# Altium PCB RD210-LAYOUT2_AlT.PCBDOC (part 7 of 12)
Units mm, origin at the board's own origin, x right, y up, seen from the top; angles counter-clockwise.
Board outline 250 x 123 mm, 4 copper layers (TOP, Mid-Layer 1, Mid-Layer 2, BOTTOM), stack 0.711 mm thick; 1043 components, 659 nets, 2786 pads, 1228 vias.
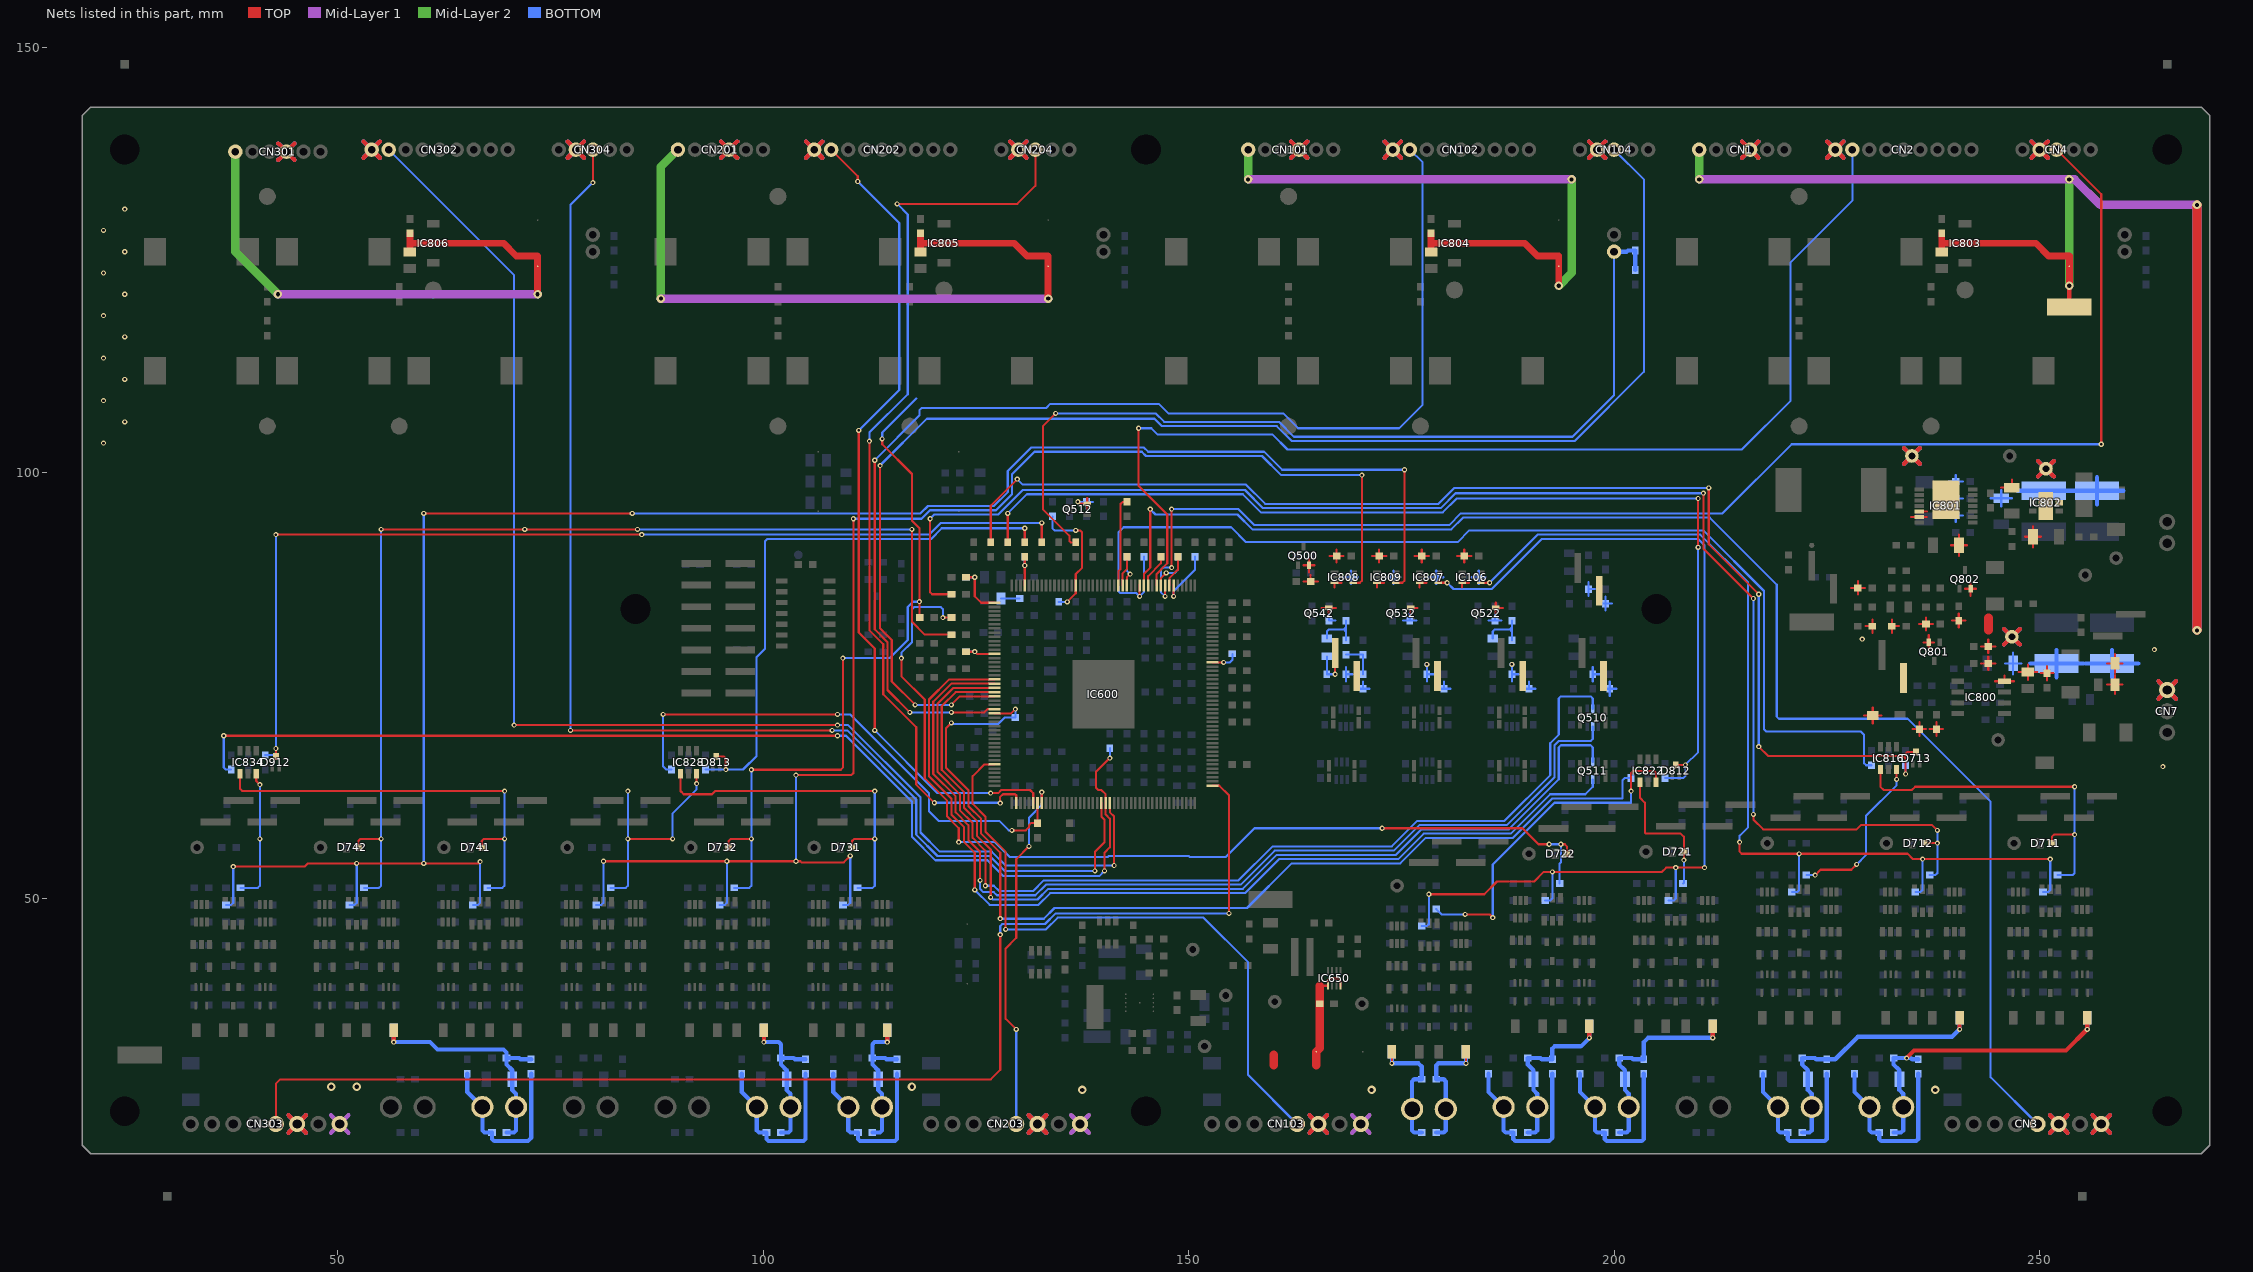
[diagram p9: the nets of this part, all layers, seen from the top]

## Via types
v1: diameter 0.6, hole 0.3, TOP to BOTTOM, 1134 vias
v2: diameter 1, hole 0.5, TOP to BOTTOM, 94 vias

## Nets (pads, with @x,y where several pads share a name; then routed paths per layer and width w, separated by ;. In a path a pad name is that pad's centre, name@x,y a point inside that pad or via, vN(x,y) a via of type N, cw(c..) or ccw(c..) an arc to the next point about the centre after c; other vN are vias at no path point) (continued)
GND: C501.1 C502.1 C517.1 C518.1 C527.1 C528.1 C537.1 C538.1 C547.1 C548.1 C635.1 C636.1 C637.1 C648.1 C650.2 C651.1 C801.1 C812.1 C813.1 C814.2 C816.1 C817.1 C818.1 C819.1 C820.1 C836.1 C837.1 CN1.3 CN2.9 CN3.3 CN4.4 CN101.3 CN102.9 CN103.3 CN104.4 CN201.3 CN202.9 CN203.3 CN204.4 CN301.3 CN302.9 CN303.3 CN304.4 CN400.2 CN500.2 CN510.2 CN520.2 CN530.2 CN540.2 CN955.1 CN956.1 IC106.3 IC650.5 IC650.8 IC801.5 IC801.6 IC801.15 IC802.2 IC802.7 IC807.3 IC808.3 IC809.3 pad.@178,77.5 pad.@188,77.5 Q500.2 Q512.2 Q522.2 Q532.2 Q542.2 Q801.2 Q802.2 R505.1 R568.1 R578.1 R588.1 R598.1 R635.2 R636.2 R637.2 R648.2 R803.1 R811.1 R815.1 | length 547.6
  TOP w0.25: 137.275,96.4 Q512.2@138.1,96.4 ; 138.1,95.775 Q512.2@138.1,96.4 ; 138.1,97.025 Q512.2@138.1,96.4 ; 163.525,87.25 R505.1@164.35,87.25 ; 163.525,89.15 Q500.2@164.15,89.15 ; 164.15,88.325 Q500.2@164.15,89.15 ; 164.15,89.975 Q500.2@164.15,89.15 ; 164.35,88.025 R505.1@164.35,87.25 ; 164.775,89.15 Q500.2@164.15,89.15 ; 165.175,87.25 R505.1@164.35,87.25 ; 165.65,39.5 165.4,39.75 IC650.5@166.375,39.75 ; 165.65,84.15 Q542.2@166.475,84.15 ; IC650.5@166.375,39.5 IC650.5@166.375,39.75 ; 166.475,83.525 Q542.2@166.475,84.15 ; 166.575,90.25 C636.1@167.4,90.25 ; 167.15,86.575 IC808.3@167.15,87.1 167.975,87.1 ; 167.3,84.15 Q542.2@166.475,84.15 ; 167.4,89.475 C636.1@167.4,90.25 ; 167.4,91.025 C636.1@167.4,90.25 ; IC650.8@167.875,39.75 167.875,40.375 167.625,40.625 166.625,40.625 166.375,40.375 IC650.5@166.375,39.75 ; 168.225,90.25 C636.1@167.4,90.25 ; 171.575,90.25 C637.1@172.4,90.25 ; 172.15,86.575 IC809.3@172.15,87.1 172.975,87.1 ; 172.4,89.475 C637.1@172.4,90.25 ; 172.4,91.025 C637.1@172.4,90.25 ; 173.225,90.25 C637.1@172.4,90.25 ; 176.1,83.525 Q532.2@176.1,84.15 176.925,84.15 ; 176.575,90.25 C635.1@177.4,90.25 ; 177.15,86.575 IC807.3@177.15,87.1 177.975,87.1 ; 177.4,89.475 C635.1@177.4,90.25 ; 177.4,91.025 C635.1@177.4,90.25 ; 178.225,90.25 C635.1@177.4,90.25 ; 181.575,90.25 C648.1@182.4,90.25 ; 182.15,86.575 IC106.3@182.15,87.1 182.975,87.1 ; 182.4,89.475 C648.1@182.4,90.25 ; 182.4,91.025 C648.1@182.4,90.25 ; 183.225,90.25 C648.1@182.4,90.25 ; 186.1,83.525 Q522.2@186.1,84.15 ; 186.1,84.775 Q522.2@186.1,84.15 ; 186.925,84.15 Q522.2@186.1,84.15 ; 227.825,86.5 C819.1@228.65,86.5 ; 228.65,85.725 C819.1@228.65,86.5 ; 228.65,87.275 C819.1@228.65,86.5 ; 229.475,86.5 C819.1@228.65,86.5 ; 229.525,82 C801.1@230.35,82 ; 230.35,81.225 C801.1@230.35,82 ; 230.35,82.775 C801.1@230.35,82 ; 232.65,81.225 C820.1@232.65,82 ; 232.65,82.775 C820.1@232.65,82 ; 233.475,82 C820.1@232.65,82 ; 234.925,94.825 IC801.6@235.85,94.825 236.775,94.825 ; 235.825,82.25 R803.1@236.65,82.25 ; IC801.5@235.85,95.475 236.775,95.475 ; 236.35,80.1 Q801.2@236.975,80.1 ; 236.65,81.475 R803.1@236.65,82.25 ; 236.65,83.025 R803.1@236.65,82.25 ; 236.975,79.275 Q801.2@236.975,80.1 ; 236.975,80.925 Q801.2@236.975,80.1 ; 237.475,82.25 R803.1@236.65,82.25 ; 237.6,80.1 Q801.2@236.975,80.1 ; 239.575,91.5 C818.1@240.525,91.5 ; 239.725,82.65 R811.1@240.5,82.65 ; 240.5,81.825 R811.1@240.5,82.65 ; 240.5,83.475 R811.1@240.5,82.65 ; 240.525,90.225 C818.1@240.525,91.5 ; 240.525,92.775 C818.1@240.525,91.5 ; 241.275,82.65 R811.1@240.5,82.65 ; 241.275,86.4 Q802.2@241.9,86.4 ; 241.475,91.5 C818.1@240.525,91.5 ; 241.9,85.575 Q802.2@241.9,86.4 ; 241.9,87.225 Q802.2@241.9,86.4 ; 242.525,86.4 Q802.2@241.9,86.4 ; 245.475,98.275 C816.1@246.75,98.275 246.75,99.225 ; 248.275,92.5 C814.2@249.225,92.5 ; 249.225,91.225 C814.2@249.225,92.5 ; 249.225,93.775 C814.2@249.225,92.5 ; 250.175,92.5 C814.2@249.225,92.5
  TOP w0.5: 43.045,136.795 CN301.3@44,137.75 ; 43.045,138.705 CN301.3@44,137.75 ; 44.225,22.475 CN303.3@45.25,23.5 ; 44.225,24.525 CN303.3@45.25,23.5 ; 44.955,136.795 CN301.3@44,137.75 ; 44.955,138.705 CN301.3@44,137.75 ; 46.275,22.475 CN303.3@45.25,23.5 ; 46.275,24.525 CN303.3@45.25,23.5 ; 53.045,137.045 CN302.9@54,138 ; 53.045,138.955 CN302.9@54,138 ; 54.955,137.045 CN302.9@54,138 ; 54.955,138.955 CN302.9@54,138 ; 77.045,137.045 CN304.4@78,138 ; 77.045,138.955 CN304.4@78,138 ; 78.955,137.045 CN304.4@78,138 ; 78.955,138.955 CN304.4@78,138 ; 95.045,137.045 CN201.3@96,138 ; 95.045,138.955 CN201.3@96,138 ; 96.955,137.045 CN201.3@96,138 ; 96.955,138.955 CN201.3@96,138 ; 105.045,137.045 CN202.9@106,138 ; 105.045,138.955 CN202.9@106,138 ; 106.955,137.045 CN202.9@106,138 ; 106.955,138.955 CN202.9@106,138 ; 129.045,137.045 CN204.4@130,138 ; 129.045,138.955 CN204.4@130,138 ; 130.955,137.045 CN204.4@130,138 ; 130.955,138.955 CN204.4@130,138 ; 131.225,22.475 CN203.3@132.25,23.5 ; 131.225,24.525 CN203.3@132.25,23.5 ; 133.275,22.475 CN203.3@132.25,23.5 ; 133.275,24.525 CN203.3@132.25,23.5 ; 162.045,137.045 CN101.3@163,138 ; 162.045,138.955 CN101.3@163,138 ; 163.955,137.045 CN101.3@163,138 ; 163.955,138.955 CN101.3@163,138 ; 164.225,22.475 CN103.3@165.25,23.5 ; 164.225,24.525 CN103.3@165.25,23.5 ; 166.275,22.475 CN103.3@165.25,23.5 ; 166.275,24.525 CN103.3@165.25,23.5 ; 173.045,137.045 CN102.9@174,138 ; 173.045,138.955 CN102.9@174,138 ; 174.955,137.045 CN102.9@174,138 ; 174.955,138.955 CN102.9@174,138 ; 197.045,137.045 CN104.4@198,138 ; 197.045,138.955 CN104.4@198,138 ; 198.955,137.045 CN104.4@198,138 ; 198.955,138.955 CN104.4@198,138 ; 215.045,137.045 CN1.3@216,138 ; 215.045,138.955 CN1.3@216,138 ; 216.955,137.045 CN1.3@216,138 ; 216.955,138.955 CN1.3@216,138 ; 225.045,137.045 CN2.9@226,138 ; 225.045,138.955 CN2.9@226,138 ; 226.955,137.045 CN2.9@226,138 ; 226.955,138.955 CN2.9@226,138 ; 234.081,101.081 CN956.1@235,102 ; 234.081,102.919 CN956.1@235,102 ; 235.919,101.081 CN956.1@235,102 ; 235.919,102.919 CN956.1@235,102 ; 249.045,137.045 CN4.4@250,138 ; 249.045,138.955 CN4.4@250,138 ; 249.831,99.581 CN955.1@250.75,100.5 ; 249.831,101.419 CN955.1@250.75,100.5 ; 250.955,137.045 CN4.4@250,138 ; 250.955,138.955 CN4.4@250,138 ; 251.225,22.475 CN3.3@252.25,23.5 ; 251.225,24.525 CN3.3@252.25,23.5 ; 251.669,99.581 CN955.1@250.75,100.5 ; 251.669,101.419 CN955.1@250.75,100.5 ; 253.275,22.475 CN3.3@252.25,23.5 ; 253.275,24.525 CN3.3@252.25,23.5
  TOP w1: 160,30.375 160,31.625 ; 165.025,30.375 C650.2@165.025,32 165.4,32.375 C651.1@165.4,37.625 165.4,39.75 ; 244,81.5 244,83
  Mid-Layer 1 w0.5: 43.045,136.795 CN301.3@44,137.75 ; 43.045,138.705 CN301.3@44,137.75 ; 44.225,22.475 CN303.3@45.25,23.5 ; 44.225,24.525 CN303.3@45.25,23.5 ; 44.955,136.795 CN301.3@44,137.75 ; 44.955,138.705 CN301.3@44,137.75 ; 46.275,22.475 CN303.3@45.25,23.5 ; 46.275,24.525 CN303.3@45.25,23.5 ; 53.045,137.045 CN302.9@54,138 ; 53.045,138.955 CN302.9@54,138 ; 54.955,137.045 CN302.9@54,138 ; 54.955,138.955 CN302.9@54,138 ; 77.045,137.045 CN304.4@78,138 ; 77.045,138.955 CN304.4@78,138 ; 78.955,137.045 CN304.4@78,138 ; 78.955,138.955 CN304.4@78,138 ; 95.045,137.045 CN201.3@96,138 ; 95.045,138.955 CN201.3@96,138 ; 96.955,138.955 CN201.3@96,138 ; 105.045,137.045 CN202.9@106,138 ; 105.045,138.955 CN202.9@106,138 ; 106.955,137.045 CN202.9@106,138 ; 106.955,138.955 CN202.9@106,138 ; 129.045,137.045 CN204.4@130,138 ; 129.045,138.955 CN204.4@130,138 ; 130.955,137.045 CN204.4@130,138 ; 130.955,138.955 CN204.4@130,138 ; 131.225,22.475 CN203.3@132.25,23.5 ; 131.225,24.525 CN203.3@132.25,23.5 ; 133.275,22.475 CN203.3@132.25,23.5 ; 133.275,24.525 CN203.3@132.25,23.5 ; 162.045,137.045 CN101.3@163,138 ; 162.045,138.955 CN101.3@163,138 ; 163.955,138.955 CN101.3@163,138 ; 164.225,22.475 CN103.3@165.25,23.5 ; 164.225,24.525 CN103.3@165.25,23.5 ; 166.275,22.475 CN103.3@165.25,23.5 ; 166.275,24.525 CN103.3@165.25,23.5 ; 173.045,137.045 CN102.9@174,138 ; 173.045,138.955 CN102.9@174,138 ; 174.955,137.045 CN102.9@174,138 ; 174.955,138.955 CN102.9@174,138 ; 197.045,137.045 CN104.4@198,138 ; 197.045,138.955 CN104.4@198,138 ; 198.955,137.045 CN104.4@198,138 ; 198.955,138.955 CN104.4@198,138 ; 215.045,137.045 CN1.3@216,138 ; 215.045,138.955 CN1.3@216,138 ; 216.955,138.955 CN1.3@216,138 ; 225.045,137.045 CN2.9@226,138 ; 225.045,138.955 CN2.9@226,138 ; 226.955,137.045 CN2.9@226,138 ; 226.955,138.955 CN2.9@226,138 ; 234.081,101.081 CN956.1@235,102 ; 234.081,102.919 CN956.1@235,102 ; 235.919,101.081 CN956.1@235,102 ; 235.919,102.919 CN956.1@235,102 ; 249.045,137.045 CN4.4@250,138 ; 249.045,138.955 CN4.4@250,138 ; 249.831,99.581 CN955.1@250.75,100.5 ; 249.831,101.419 CN955.1@250.75,100.5 ; 250.955,137.045 CN4.4@250,138 ; 250.955,138.955 CN4.4@250,138 ; 251.225,22.475 CN3.3@252.25,23.5 ; 251.225,24.525 CN3.3@252.25,23.5 ; 251.669,99.581 CN955.1@250.75,100.5 ; 251.669,101.419 CN955.1@250.75,100.5 ; 253.275,22.475 CN3.3@252.25,23.5 ; 253.275,24.525 CN3.3@252.25,23.5
  Mid-Layer 2 w0.5: 43.045,136.795 CN301.3@44,137.75 ; 43.045,138.705 CN301.3@44,137.75 ; 44.225,22.475 CN303.3@45.25,23.5 ; 44.225,24.525 CN303.3@45.25,23.5 ; 44.955,136.795 CN301.3@44,137.75 ; 44.955,138.705 CN301.3@44,137.75 ; 46.275,22.475 CN303.3@45.25,23.5 ; 46.275,24.525 CN303.3@45.25,23.5 ; 53.045,137.045 CN302.9@54,138 ; 53.045,138.955 CN302.9@54,138 ; 54.955,137.045 CN302.9@54,138 ; 54.955,138.955 CN302.9@54,138 ; 77.045,137.045 CN304.4@78,138 ; 77.045,138.955 CN304.4@78,138 ; 78.955,137.045 CN304.4@78,138 ; 78.955,138.955 CN304.4@78,138 ; 95.045,137.045 CN201.3@96,138 ; 95.045,138.955 CN201.3@96,138 ; 96.955,137.045 CN201.3@96,138 ; 96.955,138.955 CN201.3@96,138 ; 105.045,137.045 CN202.9@106,138 ; 105.045,138.955 CN202.9@106,138 ; 106.955,137.045 CN202.9@106,138 ; 106.955,138.955 CN202.9@106,138 ; 129.045,137.045 CN204.4@130,138 ; 129.045,138.955 CN204.4@130,138 ; 130.955,137.045 CN204.4@130,138 ; 130.955,138.955 CN204.4@130,138 ; 131.225,22.475 CN203.3@132.25,23.5 ; 131.225,24.525 CN203.3@132.25,23.5 ; 133.275,22.475 CN203.3@132.25,23.5 ; 133.275,24.525 CN203.3@132.25,23.5 ; 162.045,137.045 CN101.3@163,138 ; 162.045,138.955 CN101.3@163,138 ; 163.955,137.045 CN101.3@163,138 ; 163.955,138.955 CN101.3@163,138 ; 164.225,22.475 CN103.3@165.25,23.5 ; 164.225,24.525 CN103.3@165.25,23.5 ; 166.275,22.475 CN103.3@165.25,23.5 ; 166.275,24.525 CN103.3@165.25,23.5 ; 173.045,137.045 CN102.9@174,138 ; 173.045,138.955 CN102.9@174,138 ; 174.955,137.045 CN102.9@174,138 ; 174.955,138.955 CN102.9@174,138 ; 197.045,137.045 CN104.4@198,138 ; 197.045,138.955 CN104.4@198,138 ; 198.955,137.045 CN104.4@198,138 ; 198.955,138.955 CN104.4@198,138 ; 215.045,137.045 CN1.3@216,138 ; 215.045,138.955 CN1.3@216,138 ; 216.955,137.045 CN1.3@216,138 ; 216.955,138.955 CN1.3@216,138 ; 225.045,137.045 CN2.9@226,138 ; 225.045,138.955 CN2.9@226,138 ; 226.955,137.045 CN2.9@226,138 ; 226.955,138.955 CN2.9@226,138 ; 234.081,101.081 CN956.1@235,102 ; 234.081,102.919 CN956.1@235,102 ; 235.919,101.081 CN956.1@235,102 ; 235.919,102.919 CN956.1@235,102 ; 249.045,137.045 CN4.4@250,138 ; 249.045,138.955 CN4.4@250,138 ; 249.831,99.581 CN955.1@250.75,100.5 ; 249.831,101.419 CN955.1@250.75,100.5 ; 250.955,137.045 CN4.4@250,138 ; 250.955,138.955 CN4.4@250,138 ; 251.225,22.475 CN3.3@252.25,23.5 ; 251.225,24.525 CN3.3@252.25,23.5 ; 251.669,99.581 CN955.1@250.75,100.5 ; 251.669,101.419 CN955.1@250.75,100.5 ; 253.275,22.475 CN3.3@252.25,23.5 ; 253.275,24.525 CN3.3@252.25,23.5
  BOTTOM w0.25: v1@137.225,96.6 R568.1@138,96.6 ; 138,95.775 R568.1@138,96.6 ; 138.775,96.6 R568.1@138,96.6 ; 166.5,83.475 R598.1@166.5,82.65 167.275,82.65 ; 168.275,87.75 R636.2@169.1,87.75 ; 168.5,75.525 C547.1@168.5,76.35 ; 168.5,77.175 C547.1@168.5,76.35 ; 169.1,86.975 R636.2@169.1,87.75 ; 169.1,88.525 R636.2@169.1,87.75 ; 169.275,76.35 C547.1@168.5,76.35 ; 169.725,74.65 C548.1@170.5,74.65 ; 169.925,87.75 R636.2@169.1,87.75 ; 170.5,75.475 C548.1@170.5,74.65 ; 171.275,74.65 C548.1@170.5,74.65 ; 173.275,87.75 R637.2@174.1,87.75 ; 174.1,86.975 R637.2@174.1,87.75 ; 174.1,88.525 R637.2@174.1,87.75 ; 174.925,87.75 R637.2@174.1,87.75 ; 175.225,82.65 R588.1@176,82.65 ; 176,83.475 R588.1@176,82.65 ; 176.775,82.65 R588.1@176,82.65 ; 178,75.525 C537.1@178,76.35 ; 178,77.175 C537.1@178,76.35 ; 178.275,87.75 R635.2@179.1,87.75 ; 178.775,76.35 C537.1@178,76.35 ; 179.1,86.975 R635.2@179.1,87.75 ; 179.1,88.525 R635.2@179.1,87.75 ; 179.225,74.65 C538.1@180,74.65 ; 179.925,87.75 R635.2@179.1,87.75 ; 180,75.475 C538.1@180,74.65 ; 180.775,74.65 C538.1@180,74.65 ; 183.275,87.75 R648.2@184.1,87.75 ; 184.1,86.975 R648.2@184.1,87.75 ; 184.1,88.525 R648.2@184.1,87.75 ; 184.925,87.75 R648.2@184.1,87.75 ; 185.225,82.65 R578.1@186,82.65 ; 186,83.475 R578.1@186,82.65 ; 186.775,82.65 R578.1@186,82.65 ; 188,75.525 C527.1@188,76.35 ; 188,77.175 C527.1@188,76.35 ; 188.775,76.35 C527.1@188,76.35 ; 189.225,74.65 C528.1@190,74.65 ; 190,75.475 C528.1@190,74.65 ; 190.775,74.65 C528.1@190,74.65 ; 197,85.525 C501.1@197,86.35 ; 197,87.175 C501.1@197,86.35 ; 197.5,75.525 C517.1@197.5,76.35 ; 197.5,77.175 C517.1@197.5,76.35 ; 197.775,86.35 C501.1@197,86.35 ; 198.225,84.65 C502.1@199,84.65 ; 198.275,76.35 C517.1@197.5,76.35 ; 198.725,74.65 C518.1@199.5,74.65 ; 199,83.825 C502.1@199,84.65 ; 199,85.475 C502.1@199,84.65 ; 199.5,73.825 C518.1@199.5,74.65 ; 199.5,75.475 C518.1@199.5,74.65 ; 199.775,84.65 C502.1@199,84.65 ; 200.275,74.65 C518.1@199.5,74.65 ; 239.325,95 R815.1@240.15,95 ; 239.325,97 C813.1@240.15,97 ; 239.325,99 C817.1@240.15,99 ; 240.15,94.225 R815.1@240.15,95 ; 240.15,95.775 R815.1@240.15,95 ; 240.15,96.225 C813.1@240.15,97 ; 240.15,97.775 C813.1@240.15,97 ; 240.15,98.225 C817.1@240.15,99 ; 240.15,99.775 C817.1@240.15,99 ; 240.975,95 R815.1@240.15,95 ; 240.975,97 C813.1@240.15,97 ; 240.975,99 C817.1@240.15,99 ; 244.225,97.025 C812.1@245.5,97.025 ; 245.5,96.075 C812.1@245.5,97.025 ; 245.5,97.975 C812.1@245.5,97.025 ; 246.775,97.025 C812.1@245.5,97.025
  BOTTOM w0.5: 43.045,136.795 CN301.3@44,137.75 ; 43.045,138.705 CN301.3@44,137.75 ; 44.225,22.475 CN303.3@45.25,23.5 ; 44.225,24.525 CN303.3@45.25,23.5 ; 44.955,136.795 CN301.3@44,137.75 ; 44.955,138.705 CN301.3@44,137.75 ; 46.275,22.475 CN303.3@45.25,23.5 ; 46.275,24.525 CN303.3@45.25,23.5 ; 53.045,137.045 CN302.9@54,138 ; 53.045,138.955 CN302.9@54,138 ; 54.955,137.045 CN302.9@54,138 ; 54.955,138.955 CN302.9@54,138 ; 77.045,137.045 CN304.4@78,138 ; 77.045,138.955 CN304.4@78,138 ; 78.955,137.045 CN304.4@78,138 ; 78.955,138.955 CN304.4@78,138 ; 95.045,137.045 CN201.3@96,138 ; 95.045,138.955 CN201.3@96,138 ; 96.955,137.045 CN201.3@96,138 ; 96.955,138.955 CN201.3@96,138 ; 105.045,137.045 CN202.9@106,138 ; 105.045,138.955 CN202.9@106,138 ; 106.955,137.045 CN202.9@106,138 ; 106.955,138.955 CN202.9@106,138 ; 129.045,137.045 CN204.4@130,138 ; 129.045,138.955 CN204.4@130,138 ; 130.955,137.045 CN204.4@130,138 ; 130.955,138.955 CN204.4@130,138 ; 131.225,22.475 CN203.3@132.25,23.5 ; 131.225,24.525 CN203.3@132.25,23.5 ; 133.275,22.475 CN203.3@132.25,23.5 ; 133.275,24.525 CN203.3@132.25,23.5 ; 162.045,137.045 CN101.3@163,138 ; 162.045,138.955 CN101.3@163,138 ; 163.955,137.045 CN101.3@163,138 ; 163.955,138.955 CN101.3@163,138 ; 164.225,22.475 CN103.3@165.25,23.5 ; 164.225,24.525 CN103.3@165.25,23.5 ; 166.275,22.475 CN103.3@165.25,23.5 ; 166.275,24.525 CN103.3@165.25,23.5 ; 173.045,137.045 CN102.9@174,138 ; 173.045,138.955 CN102.9@174,138 ; 174.955,137.045 CN102.9@174,138 ; 174.955,138.955 CN102.9@174,138 ; 197.045,137.045 CN104.4@198,138 ; 197.045,138.955 CN104.4@198,138 ; 198.955,137.045 CN104.4@198,138 ; 198.955,138.955 CN104.4@198,138 ; 215.045,137.045 CN1.3@216,138 ; 215.045,138.955 CN1.3@216,138 ; 216.955,137.045 CN1.3@216,138 ; 216.955,138.955 CN1.3@216,138 ; 225.045,137.045 CN2.9@226,138 ; 225.045,138.955 CN2.9@226,138 ; 226.955,137.045 CN2.9@226,138 ; 226.955,138.955 CN2.9@226,138 ; 234.081,101.081 CN956.1@235,102 235.919,101.081 ; 247.4,97.9 C837.1@250.5,97.9 ; 249.045,137.045 CN4.4@250,138 ; 249.045,138.955 CN4.4@250,138 ; 249.831,99.581 CN955.1@250.75,100.5 ; 249.831,101.419 CN955.1@250.75,100.5 ; 250.5,96.3 C837.1@250.5,97.9 ; 250.955,137.045 CN4.4@250,138 ; 250.955,138.955 CN4.4@250,138 ; 251.225,22.475 CN3.3@252.25,23.5 ; 251.225,24.525 CN3.3@252.25,23.5 ; 251.669,99.581 CN955.1@250.75,100.5 ; 251.669,101.419 CN955.1@250.75,100.5 ; 253.275,22.475 CN3.3@252.25,23.5 ; 253.275,24.525 CN3.3@252.25,23.5 ; 253.6,97.9 C837.1@250.5,97.9 ; 253.65,97.9 C836.1@256.75,97.9 ; 256.75,96.3 C836.1@256.75,97.9 ; 256.75,99.5 C836.1@256.75,97.9 ; 259.85,97.9 C836.1@256.75,97.9
  other v1: 178,77.5 188,77.5 229.169,80.485 137,96.625 22.5,103.5 25,106 22.5,108.5 25,111 22.5,113.5 25,116 22.5,118.5 25,121 22.5,123.5 25,126 22.5,128.5 25,131
  other v2: 137.5,27.5 171.5,27.5 237.75,27.5 49.25,27.875 52.25,27.875 117.5,27.875
GND_P0: C802.1 C803.1 C804.1 C805.2 C808.1 C809.1 C810.1 C811.1 C821.2 C825.1 C829.1 CN1.6 CN3.1 CN7.3 CN103.1 CN203.1 CN303.1 CN953.1 CN960.1 D808.1 IC800.4 IC803.2 R804.2 R805.1 R809.1 | length 453.8
  TOP w0.25: 229.375,71.5 D808.1@230.4,71.5 ; 230.4,70.575 D808.1@230.4,71.5 ; 230.4,72.425 D808.1@230.4,71.5 ; 231.425,71.5 D808.1@230.4,71.5 ; 235.1,69.9 R804.2@235.875,69.9 ; 235.875,69.075 R804.2@235.875,69.9 ; 235.875,70.725 R804.2@235.875,69.9 ; 236.65,69.9 R804.2@235.875,69.9 ; 237.1,69.9 C805.2@237.875,69.9 ; 237.875,69.075 C805.2@237.875,69.9 ; 237.875,70.725 C805.2@237.875,69.9 ; 238.65,69.9 C805.2@237.875,69.9 ; 243.15,77.625 R809.1@243.975,77.625 ; 243.15,79.625 R805.1@243.975,79.625 ; 243.975,76.85 R809.1@243.975,77.625 ; 243.975,78.4 R809.1@243.975,77.625 ; 243.975,78.85 R805.1@243.975,79.625 ; 243.975,80.4 R805.1@243.975,79.625 ; 244.75,75.53 IC800.4@245.875,75.53 ; 244.8,77.625 R809.1@243.975,77.625 ; 244.8,79.625 R805.1@243.975,79.625 ; 245.875,76.205 IC800.4@245.875,75.53 ; 247,75.53 IC800.4@245.875,75.53 ; 247.525,76.6 C809.1@248.625,76.6 ; 248.625,75.7 C809.1@248.625,76.6 ; 248.625,77.5 C809.1@248.625,76.6 ; 249.725,76.6 C809.1@248.625,76.6 ; 250.1,76.475 C804.1@250.875,76.475 ; 250.875,75.65 C804.1@250.875,76.475 ; 250.875,77.3 C804.1@250.875,76.475 ; 251.65,76.475 C804.1@250.875,76.475 ; 257.95,75.125 C803.1@258.85,75.125 ; 257.95,77.625 C802.1@258.85,77.625 ; 258.85,74.025 C803.1@258.85,75.125 ; 258.85,76.225 C803.1@258.85,75.125 ; 258.85,76.525 C802.1@258.85,77.625 ; 258.85,78.725 C802.1@258.85,77.625 ; 259.75,75.125 C803.1@258.85,75.125 ; 259.75,77.625 C802.1@258.85,77.625
  TOP w0.5: 245.831,79.831 CN953.1@246.75,80.75 ; 245.831,81.669 CN953.1@246.75,80.75 ; 247.669,79.831 CN953.1@246.75,80.75 ; 247.669,81.669 CN953.1@246.75,80.75 ; CN960.1@253.5,119.5 v2(253.5,122) ; 256.225,22.475 CN3.1@257.25,23.5 ; 256.225,24.525 CN3.1@257.25,23.5 ; 258.275,22.475 CN3.1@257.25,23.5 ; 258.275,24.525 CN3.1@257.25,23.5 ; 263.975,73.475 CN7.3@265,74.5 ; 263.975,75.525 CN7.3@265,74.5 ; 266.025,73.475 CN7.3@265,74.5 ; 266.025,75.525 CN7.3@265,74.5
  TOP w0.8: C829.1@238.5,125.975 238.5,127 ; C825.1@238.5,128.15 238.5,127 ; v2(253.5,122) C821.2@253.5,124.275 253.5,125.5 251.05,125.5 249.55,127 IC803.2@241.25,127 238.5,127
  TOP w1: v2(268.5,81.5) v2(268.5,131.5)
  Mid-Layer 1 w0.5: 49.225,22.475 CN303.1@50.25,23.5 ; 49.225,24.525 CN303.1@50.25,23.5 ; 51.275,22.475 CN303.1@50.25,23.5 ; 51.275,24.525 CN303.1@50.25,23.5 ; 136.225,22.475 CN203.1@137.25,23.5 ; 136.225,24.525 CN203.1@137.25,23.5 ; 138.275,22.475 CN203.1@137.25,23.5 ; 138.275,24.525 CN203.1@137.25,23.5 ; 169.225,22.475 CN103.1@170.25,23.5 ; 169.225,24.525 CN103.1@170.25,23.5 ; 171.275,22.475 CN103.1@170.25,23.5 ; 171.275,24.525 CN103.1@170.25,23.5 ; 245.831,79.831 CN953.1@246.75,80.75 ; 245.831,81.669 CN953.1@246.75,80.75 ; 247.669,79.831 CN953.1@246.75,80.75 ; 247.669,81.669 CN953.1@246.75,80.75 ; 256.225,22.475 CN3.1@257.25,23.5 ; 256.225,24.525 CN3.1@257.25,23.5 ; 258.275,22.475 CN3.1@257.25,23.5 ; 258.275,24.525 CN3.1@257.25,23.5 ; 263.975,73.475 CN7.3@265,74.5 ; 263.975,75.525 CN7.3@265,74.5 ; 266.025,73.475 CN7.3@265,74.5 ; 266.025,75.525 CN7.3@265,74.5
  Mid-Layer 1 w1: v2(210,134.5) v2(253.5,134.5) 254.125,134.5 257.125,131.5 v2(268.5,131.5) v2(268.5,81.5)
  Mid-Layer 2 w0.5: 136.225,22.475 CN203.1@137.25,23.5 ; 136.225,24.525 CN203.1@137.25,23.5 ; 138.275,22.475 CN203.1@137.25,23.5 ; 138.275,24.525 CN203.1@137.25,23.5 ; 169.225,22.475 CN103.1@170.25,23.5 ; 169.225,24.525 CN103.1@170.25,23.5 ; 171.275,22.475 CN103.1@170.25,23.5 ; 171.275,24.525 CN103.1@170.25,23.5 ; 245.831,79.831 CN953.1@246.75,80.75 ; 245.831,81.669 CN953.1@246.75,80.75 ; 247.669,79.831 CN953.1@246.75,80.75 ; 247.669,81.669 CN953.1@246.75,80.75 ; 256.225,22.475 CN3.1@257.25,23.5 ; 256.225,24.525 CN3.1@257.25,23.5 ; 258.275,22.475 CN3.1@257.25,23.5 ; 258.275,24.525 CN3.1@257.25,23.5 ; 263.975,73.475 CN7.3@265,74.5 ; 263.975,75.525 CN7.3@265,74.5 ; 266.025,73.475 CN7.3@265,74.5 ; 266.025,75.525 CN7.3@265,74.5
  Mid-Layer 2 w1: v2(210,134.5) CN1.6@210,138 ; v2(253.5,122) v2(253.5,134.5) ; v2(268.5,81.5) v2(268.5,131.5)
  BOTTOM w0.25: 245.95,77.625 C808.1@246.9,77.625 ; 246.9,76.35 C808.1@246.9,77.625 ; 246.9,78.9 C808.1@246.9,77.625 ; 247.85,77.625 C808.1@246.9,77.625
  BOTTOM w0.5: 245.831,79.831 CN953.1@246.75,80.75 ; 245.831,81.669 CN953.1@246.75,80.75 ; 247.669,79.831 CN953.1@246.75,80.75 ; 247.669,81.669 CN953.1@246.75,80.75 ; 248.9,77.6 C810.1@252,77.6 ; 252,76 C810.1@252,77.6 ; 252,79.2 C810.1@252,77.6 ; 255.1,77.6 C810.1@252,77.6 ; 255.4,77.6 C811.1@258.5,77.6 ; 256.225,22.475 CN3.1@257.25,23.5 ; 256.225,24.525 CN3.1@257.25,23.5 ; 258.275,22.475 CN3.1@257.25,23.5 ; 258.275,24.525 CN3.1@257.25,23.5 ; 258.5,76 C811.1@258.5,77.6 ; 258.5,79.2 C811.1@258.5,77.6 ; 261.6,77.6 C811.1@258.5,77.6 ; 263.975,73.475 CN7.3@265,74.5 ; 263.975,75.525 CN7.3@265,74.5 ; 266.025,73.475 CN7.3@265,74.5 ; 266.025,75.525 CN7.3@265,74.5
  BOTTOM w1: v2(268.5,81.5) v2(268.5,131.5)
  other v1: 264.5,65.5 263.5,79.25
GND_P1: C822.2 C826.1 C830.1 CN101.6 IC804.2 | length 75.9
  TOP w0.8: C830.1@178.5,125.975 178.5,127 ; C826.1@178.5,128.15 178.5,127 ; v2(193.5,122) C822.2@193.5,124.275 193.5,125.5 191,125.5 189.5,127 IC804.2@181.25,127 178.5,127
  Mid-Layer 1 w1: v2(157,134.5) v2(195,134.5)
  Mid-Layer 2 w1: v2(157,134.5) CN101.6@157,138 ; v2(193.5,122) 195,123.5 v2(195,134.5)
GND_P2: C823.2 C827.1 C831.1 CN201.6 IC805.2 | length 86.6
  TOP w0.8: C831.1@118.5,125.975 118.5,127 ; C827.1@118.5,128.15 118.5,127 ; v2(133.5,120.5) C823.2@133.5,124.275 133.5,125.5 131,125.5 129.5,127 IC805.2@121.25,127 118.5,127
  Mid-Layer 1 w1: v2(88,120.5) v2(133.5,120.5)
  Mid-Layer 2 w1: v2(88,120.5) 88,136 CN201.6@90,138
GND_P3: C824.2 C828.1 C832.1 CN301.6 IC806.2 | length 71.6
  TOP w0.8: C832.1@58.5,125.975 58.5,127 ; C828.1@58.5,128.15 58.5,127 ; v2(73.5,121) C824.2@73.5,124.275 73.5,125.5 71,125.5 69.5,127 IC806.2@61.25,127 58.5,127
  Mid-Layer 1 w1: v2(43,121) v2(73.5,121)
  Mid-Layer 2 w1: CN301.6@38,137.75 38,126 v2(43,121)
H_EN_0-1: CN4.3 IC600.8 | length 163.6
  TOP w0.25: v1(147.25,85.5) IC600.8@147.25,86.8 ; v1(148,88.875) v1(148,95.75) ; CN4.3@252,138 257.25,132.75 v1(257.25,103.375)
  BOTTOM w0.25: v1(147.25,85.5) 146.75,86 146.75,88.625 147,88.875 v1(148,88.875) ; v1(148,95.75) 155.875,95.75 157.75,93.875 180.625,93.875 182,95.25 212.75,95.25 220.875,103.375 v1(257.25,103.375)
H_EN_0-2: CN104.3 IC600.67 | length 163.6
  TOP w0.25: v1(113.75,100.875) 113.75,81.75 115.125,80.375 115.125,75.5 v1(117.875,72.75) ; v1(122.125,72.75) 123.125,73.75 IC600.67@127.2,73.75
  BOTTOM w0.25: v1(113.75,100.875) 119.25,106.375 146,106.375 146.875,105.5 160.375,105.5 162.125,103.75 195.375,103.75 203.5,111.875 203.5,134.5 CN104.3@200,138 ; v1(117.875,72.75) v1(122.125,72.75)
H_EN_0-3: CN204.3 IC600.90 | length 108.8
  TOP w0.25: v1(112.5,103.75) 112.5,81.5 114.125,79.875 114.125,74 118,70.125 118,63.375 v1(120.125,61.25) ; v1(115.75,131.625) 129.875,131.625 132,133.75 CN204.3@132,138 ; v1(127.875,61.2) 127.825,61.25 127.825,61.875 128.2,62.25 129.625,62.25 129.75,62.125 IC600.90@129.75,61.2
  BOTTOM w0.25: v1(112.5,103.75) 112.5,104.75 117,109.25 117,130.375 v1(115.75,131.625) ; v1(120.125,61.25) 127.825,61.25 v1(127.875,61.2)
H_EN_0-4: CN304.3 IC600.110 | length 148.8
  TOP w0.25: v1(77.375,69.75) v1(108.125,69.75) ; v1(80,134.125) CN304.3@80,138 ; v1(139,53.25) 139,55.5 140.125,56.625 140.125,59.25 139.75,59.625 IC600.110@139.75,61.2
  BOTTOM w0.25: v1(77.375,69.75) 77.375,131.5 v1(80,134.125) ; v1(108.125,69.75) 109.875,69.75 118,61.625 118,57.5 120.5,55 126.625,55 128.375,53.25 v1(139,53.25)
I_C0-1: IC816.3 R937.2 | length 19.5
  TOP w0.25: v1(223.625,52.75) 224.25,53.375 227.875,53.375 v1(228.5,54) ; v1(233.2,64) IC816.3@233.2,65.15
  BOTTOM w0.25: R937.2@222.6,52.75 v1(223.625,52.75) ; v1(228.5,54) 229.625,55.125 229.625,59.75 233.2,63.325 v1(233.2,64)
I_C0-2: IC822.3 R957.2 | length 40.3
  TOP w0.25: v1(182.5,48.125) 185.375,48.125 v1(185.75,47.75) ; v1(202,62.625) 202,64.75 202.25,65 204.7,65 204.95,64.75 IC822.3@204.95,63.65
  BOTTOM w0.25: R957.2@179.1,48.75 179.125,48.75 179.75,48.125 v1(182.5,48.125) ; v1(185.75,47.75) 185.75,54 193,61.25 202,61.25 v1(202,62.625)
I_C0-3: IC828.3 R977.2 | length 27.3
  TOP w0.25: v1(84.125,57) v1(89.375,57) ; v1(92.2,63.5) IC828.3@92.2,64.65
  BOTTOM w0.25: R977.2@82.1,51.25 83.875,51.25 84.125,51.5 v1(84.125,57) v1(84.125,62.625) ; v1(89.375,57) 89.375,60 92.2,62.825 v1(92.2,63.5)
I_C0-4: IC834.3 R997.2 | length 15.7
  TOP w0.25: IC834.3@40.45,64.65 40.45,63.8 v1(40.875,63.375)
  BOTTOM w0.25: R997.2@38.6,51.25 40.625,51.25 40.875,51.5 v1(40.875,57) v1(40.875,63.375)
I_H0-1: D713.3 R510.2 R906.2 | length 147.7
  TOP w0.25: R510.2@126.75,91.85 126.75,96.156 v1(129.875,99.281) ; v1(211.125,98.25) 211.125,91.625 v1(217,85.75) ; v1(217,67.848) 218.099,66.75 234,66.75 ; v1(234.25,64.625) 234.25,66.5 ; 234.25,67 234.25,66.5 ; D713.3@235.5,67.2 234.45,67.2 234,66.75 ; 234,66.75 234.25,66.5
  BOTTOM w0.25: v1(129.875,99.281) 130.531,98.625 156.75,98.625 159,96.375 179.375,96.375 181.25,98.25 v1(211.125,98.25) ; v1(217,67.848) v1(217,85.75) ; v1(234.25,64.625) R906.2@234.25,65.65
I_H0-2: D812.3 pad.@209.875,91.25 R520.2 R907.2 | length 123.8
  TOP w0.25: R520.2@128.75,91.85 v1(128.75,95.25) ; D812.3@207.25,65.7 v1(208.375,65.7) ; v1(209.875,91.25) v1(209.875,97)
  BOTTOM w0.25: v1(128.75,95.25) 131,97.5 156.375,97.5 158.5,95.375 179.875,95.375 181.5,97 v1(209.875,97) ; R907.2@206,64.15 208.15,64.15 208.375,64.375 v1(208.375,65.7) 209.875,67.2 v1(209.875,91.25)
I_H0-3: D813.3 R530.2 R908.2 | length 67.6
  TOP w0.25: D813.3@94.5,66.7 95.375,66.7 95.625,66.45 v1(95.625,65.15) ; R530.2@130.75,91.85 v1(130.75,93.5)
  BOTTOM w0.25: R908.2@93.25,65.15 v1(95.625,65.15) 97.65,65.15 99.25,66.75 99.25,78.375 100.25,79.375 100.25,92 100.5,92.25 119.75,92.25 121,93.5 v1(130.75,93.5)
I_H0-4: D912.3 R540.2 R909.2 | length 120.8
  TOP w0.25: D912.3@42.75,66.7 v1(42.75,67.625) ; v1(42.75,92.75) v1(85.75,92.75) ; R540.2@132.75,91.85 v1(132.75,94.125)
  BOTTOM w0.25: R909.2@41.5,66.85 42.5,66.85 42.75,67.1 v1(42.75,67.625) v1(42.75,92.75) ; v1(85.75,92.75) 119.5,92.75 120.875,94.125 v1(132.75,94.125)
I_H0_B-1: D711.3 IC816.1 R737.2 | length 40.9
  TOP w0.25: IC816.1@231.3,65.15 231.3,63.125 231.675,62.75 235,62.75 235.375,63.125 v1(254.125,63.125) ; D711.3@251.45,56.5 251.45,57.25 251.7,57.5 v1(254.125,57.5)
  BOTTOM w0.25: R737.2@252.1,52.75 253.875,52.75 254.125,53 v1(254.125,57.5) v1(254.125,63.125)
I_H0_B-2: D721.3 IC822.1 R757.2 | length 16.5
  TOP w0.25: IC822.1@203.05,63.65 203.05,61.825 203.625,61.25 203.625,57.75 203.75,57.625 207.825,57.625 208.2,57.25 D721.3@208.2,55.5 v1(208.2,54.5)
  BOTTOM w0.25: R757.2@208.1,51.75 208.2,51.85 v1(208.2,54.5)
I_H0_B-3: D731.3 IC828.1 R777.2 | length 41.9
  TOP w0.25: IC828.1@90.3,64.65 90.3,62.625 90.675,62.25 94,62.25 94.375,62.625 v1(113.125,62.625) ; D731.3@110.45,56 110.45,56.75 110.7,57 v1(113.125,57)
  BOTTOM w0.25: R777.2@111.1,51.25 112.875,51.25 113.125,51.5 v1(113.125,57) v1(113.125,62.625)
I_H0_B-4: D741.3 IC834.1 R797.2 | length 49.7
  TOP w0.25: IC834.1@38.55,64.65 38.55,62.875 38.8,62.625 v1(69.625,62.625) ; D741.3@66.95,56 66.95,56.75 67.2,57 v1(69.625,57)
  BOTTOM w0.25: R797.2@67.6,51.25 69.375,51.25 69.625,51.5 v1(69.625,57) v1(69.625,62.625)
I_L0-1: D712.3 R511.1 R837.2 | length 176
  TOP w0.25: v1(119.625,94.625) 119.625,86 119.875,85.75 R511.1@122.15,85.75 ; v1(210.5,97.625) 210.5,91.125 v1(216.375,85.25) ; v1(216.375,59.875) 216.375,59.276 217.526,58.125 228.5,58.125 229,58.625 237.375,58.625 v1(238,58) ; D712.3@236.45,56.5 v1(238,56.5)
  BOTTOM w0.25: v1(119.625,94.625) 120.125,95.125 127.625,95.125 130.5,98 156.625,98 158.75,95.875 179.625,95.875 181.375,97.625 v1(210.5,97.625) ; v1(216.375,59.875) v1(216.375,85.25) ; R837.2@237.1,52.75 237.75,52.75 238,53 v1(238,56.5) v1(238,58)
I_L0-2: D722.3 R521.1 R857.2 | length 116.7
  TOP w0.25: v1(116.25,78.25) 116.25,76.125 119,73.375 119,64.125 121.625,61.5 121.625,59.625 123,58.25 v1(123,56.625) ; v1(121.125,83) R521.1@122.15,83 ; v1(172.75,58.25) 189.25,58.25 191.125,56.375 v1(192.375,56.375) ; v1(193.75,56.375) 194.2,56.375 194.45,56.125 D722.3@194.45,55.25
  BOTTOM w0.25: v1(116.25,78.25) 116.25,78.875 117.5,80.125 117.5,84 117.75,84.25 120.875,84.25 121.125,84 v1(121.125,83) ; v1(123,56.625) 127.25,56.625 129,54.875 140.5,54.875 140.625,55 150,55 150.125,54.875 154.375,54.875 157.75,58.25 v1(172.75,58.25) ; v1(192.375,56.375) v1(193.75,56.375) 193.75,54.25 193.6,54.1 R857.2@193.6,51.75
I_L0-3: D732.3 R531.1 R877.2 | length 86.3
  TOP w0.25: D732.3@95.95,56 95.95,56.75 96.2,57 v1(98.625,57) ; v1(98.625,65.125) 109.125,65.125 109.375,65.375 v1(109.375,78.25) ; v1(114,104) 114,103.375 117.5,99.875 117.5,94.375 118.4,93.475 118.4,85.025 118.375,85 v1(118.375,84.875) 118.4,84.85 R531.1@118.4,83
  BOTTOM w0.25: R877.2@96.6,51.25 98.375,51.25 98.625,51.5 v1(98.625,57) v1(98.625,65.125) ; v1(109.375,78.25) 114.875,78.25 117,80.375 117,84.25 117.625,84.875 v1(118.375,84.875) ; v1(114,104) 114,104.75 118,108.75
I_L0-4: D742.3 R541.1 R897.2 | length 126.1
  TOP w0.25: D742.3@52.45,56 52.45,56.75 52.7,57 v1(55.125,57) ; v1(55.125,93.375) v1(72,93.375) v1(85.25,93.375) ; v1(117.5,93.375) 117.5,82.5 119,81 R541.1@122.15,81
  BOTTOM w0.25: R897.2@53.1,51.25 54.875,51.25 55.125,51.5 v1(55.125,57) v1(55.125,93.375) ; v1(85.25,93.375) v1(117.5,93.375)
I_SEL_1: IC106.4 R736.2 R836.2 R936.2 | length 119.3
  TOP w0.25: IC106.4@184.35,87.1 v1(185.375,87.1) ; v1(214.75,56.625) 214.75,55.5 215,55.25 v1(221.75,55.25) 234.5,55.25 235.125,54.625 v1(236.25,54.625) v1(251.25,54.625)
  BOTTOM w0.25: v1(185.375,87.1) 185.375,87.125 191,92.75 210.125,92.75 215.75,87.125 215.75,58.375 214.75,57.375 v1(214.75,56.625) ; R936.2@220.9,50.75 221.5,50.75 221.75,51 v1(221.75,55.25) ; R836.2@235.4,50.75 236,50.75 236.25,51 v1(236.25,54.625) ; R736.2@250.4,50.75 251,50.75 251.25,51 v1(251.25,54.625)
I_SEL_2: IC807.4 R756.2 R856.2 R956.2 | length 119
  TOP w0.25: v1(178.25,50.5) 184.75,50.5 186.25,52 190.625,52 191.75,53.125 v1(192.75,53.125) 205.625,53.125 206.125,53.625 v1(207.25,53.625) v1(210.625,53.625) ; IC807.4@179.35,87.1 v1(180.375,87.1)
  BOTTOM w0.25: R956.2@177.4,46.75 178,46.75 178.25,47 v1(178.25,50.5) ; v1(180.375,87.1) 180.4,87.1 181.125,86.375 185.625,86.375 191.5,92.25 209.875,92.25 210.625,91.5 v1(210.625,53.625) ; R856.2@191.9,49.75 192.5,49.75 192.75,50 v1(192.75,53.125) ; R756.2@206.4,49.75 207,49.75 207.25,50 v1(207.25,53.625)
I_SEL_3: IC808.4 R776.2 R876.2 R976.2 | length 173.4
  TOP w0.25: v1(81.25,54.375) v1(95.75,54.375) v1(103.875,54.375) 104.375,54.375 104.5,54.25 109.5,54.25 v1(110.25,55) ; v1(103.875,64.5) 110.375,64.5 110.625,64.75 v1(110.625,94.625) ; IC808.4@169.35,87.1 170.125,87.1 170.375,87.35 v1(170.375,99.75)
  BOTTOM w0.25: R976.2@80.4,49.25 81,49.25 81.25,49.5 v1(81.25,54.375) ; R876.2@94.9,49.25 95.5,49.25 95.75,49.5 v1(95.75,54.375) ; v1(103.875,54.375) v1(103.875,64.5) ; R776.2@109.4,49.25 110,49.25 110.25,49.5 v1(110.25,55) ; v1(110.625,94.625) 118.625,94.625 119.625,95.625 127.375,95.625 129.25,97.5 129.25,99.852 131.897,102.5 144.5,102.5 145,102 158.625,102 160.875,99.75 v1(170.375,99.75)
I_SEL_4: IC809.4 R796.2 R896.2 R996.2 | length 222.1
  TOP w0.25: v1(37.75,53.75) 46.16,53.75 46.536,54.125 v1(52.25,54.125) v1(60.125,54.125) 66.552,54.125 v1(66.75,54.323) ; v1(60.125,95.25) v1(84.625,95.25) ; IC809.4@174.35,87.1 175.125,87.1 175.375,87.35 v1(175.375,100.375)
  BOTTOM w0.25: R996.2@36.9,49.25 37.5,49.25 37.75,49.5 v1(37.75,53.75) ; R896.2@51.4,49.25 52,49.25 52.25,49.5 v1(52.25,54.125) ; v1(60.125,54.125) v1(60.125,95.25) ; R796.2@65.9,49.25 66.5,49.25 66.75,49.5 v1(66.75,54.323) ; v1(84.625,95.25) 118.5,95.25 119.375,96.125 127.125,96.125 128.75,97.75 128.75,100.233 131.516,103 144.75,103 145.25,102.5 158.875,102.5 161,100.375 v1(175.375,100.375)
I_SEL_CM-1: IC600.14 R506.2 R706.2 | length 128.8
  TOP w0.25: v1(144.25,85.5) IC600.14@144.25,86.8
  BOTTOM w0.25: R506.2@144.75,90.15 144.75,86 v1(144.25,85.5) 143.875,85.875 142,85.875 141.75,86.125 141.75,93 142.375,93.625 155,93.625 156.75,91.875 181.625,91.875 183,93.25 210.5,93.25 217.625,86.125 217.625,69.875 217.875,69.625 229,69.625 229.375,69.25 229.375,65.9 229.625,65.65 R706.2@230.25,65.65
I_SEL_CM-2: IC600.71 R614.1 R707.2 | length 119.7
  TOP w0.25: v1(122.125,70.625) 121.5,70 121.5,65.375 124.125,62.75 124.125,60.875 125.625,59.375 125.625,57.625 127.875,55.375 v1(127.875,47.625) ; IC600.71@127.2,71.75 129.15,71.75 v1(129.65,72.25)
  BOTTOM w0.25: v1(122.125,70.625) 122.25,70.5 127.625,70.5 128.375,71.25 R614.1@129.65,71.25 v1(129.65,72.25) ; v1(127.875,47.625) 133,47.625 134.25,48.875 156.875,48.875 162.125,54.125 174.875,54.125 177.875,57.125 188.125,57.125 192.75,61.75 201,61.75 201,63.875 201.275,64.15 R707.2@202,64.15
I_SEL_CM-3: IC600.95 R620.1 R708.2 | length 61
  TOP w0.25: v1(88.25,71.625) v1(108.75,71.625) ; v1(129.25,58) 130.875,58 131.25,58.375 131.25,58.625 131.475,58.85 R620.1@132.25,58.85 IC600.95@132.25,61.2
  BOTTOM w0.25: v1(88.25,71.625) 88.25,65.525 88.625,65.15 R708.2@89.25,65.15 ; v1(108.75,71.625) 110.25,71.625 119.5,62.375 119.5,60.25 120.625,59.125 127.75,59.125 128.875,58 v1(129.25,58)
I_SEL_CM-4: IC600.111 R623.1 R709.2 | length 133.9
  TOP w0.25: v1(36.625,69.125) v1(108.75,69.125) ; v1(140.125,53.25) 140.125,55.375 140.75,56 140.75,59.375 140.25,59.875 IC600.111@140.25,61.2 140.25,62.25 139.75,62.75 139.375,62.75 139.125,63 139.125,64.875 v1(140.75,66.5)
  BOTTOM w0.25: v1(36.625,69.125) 36.625,65.4 36.875,65.15 R709.2@37.5,65.15 ; v1(108.75,69.125) 109.75,69.125 117.5,61.375 117.5,57.25 120.25,54.5 126.375,54.5 128.25,52.625 139.5,52.625 v1(140.125,53.25) ; v1(140.75,66.5) R623.1@140.75,67.65
I_SEN_N_1_1: C712.1 C713.1 C719.1 CN508.1 R730.1 R732.1 R739.2 | length 38.5
  TOP w0.5: v1(234.375,31.25) 235.25,32.125 253.1,32.125 v1(255.6,34.625) R730.1@255.6,36
  BOTTOM w0.5: C719.1@232.85,22.5 233.73,22.5 233.98,22.75 233.98,27.045 233.525,27.5 C712.1@233.525,28.75 233.525,29.825 232.85,30.5 C713.1@232.85,31.25 v1(234.375,31.25) 234.875,31.25 235.025,31.1 R739.2@235.75,31.1 ; v1(255.6,34.625) R732.1@255.6,36
I_SEN_N_1_2: C732.1 C733.1 C886.1 CN618.1 R750.1 R752.1 R759.2 | length 26.2
  TOP w0.5: v1(211.6,33.625) R750.1@211.6,35
  BOTTOM w0.5: C886.1@200.6,22.5 201.48,22.5 201.73,22.75 201.73,27.045 201.275,27.5 C732.1@201.275,28.75 201.275,29.825 200.6,30.5 C733.1@200.6,31.25 202.1,31.25 202.25,31.1 R759.2@203.5,31.1 203.5,33.125 204,33.625 v1(211.6,33.625) R752.1@211.6,35
I_SEN_N_1_3: C752.1 C753.1 C888.1 CN307.1 R770.1 R772.1 R779.2 | length 19.4
  TOP w0.5: v1(114.6,33.125) R770.1@114.6,34.5
  BOTTOM w0.5: C888.1@112.85,22.5 113.73,22.5 113.98,22.75 113.98,27.045 113.525,27.5 C752.1@113.525,28.75 113.525,29.825 112.85,30.5 C753.1@112.85,31.25 ; R772.1@114.6,34.5 v1(114.6,33.125) 113.1,33.125 112.85,32.875 C753.1@112.85,31.25 ; R779.2@115.75,31.1 114.5,31.1 114.35,31.25 C753.1@112.85,31.25
I_SEN_N_1_4: C923.1 CN920.1 R950.1 R952.1 R959.2 | length 16.2
  TOP w0.25: v1(182.6,30.625) R950.1@182.6,32
  BOTTOM w0.5: C923.1@179.1,22.5 179.98,22.5 180.23,22.75 180.23,28.5 179.98,28.75 R959.2@179.1,28.75 179.1,30.375 179.35,30.625 v1(182.6,30.625) R952.1@182.6,32
I_SEN_N_2_1: C722.1 C723.1 C729.1 CN509.1 R830.1 R832.1 R839.2 | length 33
  TOP w0.5: v1(240.6,34.625) R830.1@240.6,36
  BOTTOM w0.5: C729.1@222.1,22.5 222.98,22.5 223.23,22.75 223.23,27.045 222.775,27.5 C722.1@222.775,28.75 222.775,29.825 222.1,30.5 C723.1@222.1,31.25 223.6,31.25 223.75,31.1 R839.2@225,31.1 226,31.1 228.65,33.75 239.725,33.75 v1(240.6,34.625) R832.1@240.6,36
I_SEN_N_2_2: C742.1 C743.1 C887.1 CN208.1 R850.1 R852.1 R859.2 | length 22.1
  TOP w0.5: v1(197.1,33.625) R850.1@197.1,35
  BOTTOM w0.5: C887.1@189.85,22.5 190.73,22.5 190.98,22.75 190.98,27.045 190.525,27.5 C742.1@190.525,28.75 190.525,29.825 189.85,30.5 C743.1@189.85,31.25 191.35,31.25 191.5,31.1 R859.2@192.75,31.1 192.75,32.375 193,32.625 196.1,32.625 v1(197.1,33.625) R852.1@197.1,35
I_SEN_N_2_3: C762.1 C763.1 C889.1 CN308.1 R870.1 R872.1 R879.2 | length 19.6
  TOP w0.5: v1(100.1,33.125) R870.1@100.1,34.5
  BOTTOM w0.5: R872.1@100.1,34.5 v1(100.1,33.125) 101.85,33.125 102.1,32.875 C763.1@102.1,31.25 ; C889.1@102.1,22.5 102.98,22.5 103.23,22.75 103.23,27.045 102.775,27.5 C762.1@102.775,28.75 102.775,29.825 102.1,30.5 C763.1@102.1,31.25 ; R879.2@105,31.1 103.75,31.1 103.6,31.25 C763.1@102.1,31.25
I_SEN_N_2_4: C782.1 C783.1 C891.1 CN408.1 R890.1 R892.1 R899.2 | length 30.3
  TOP w0.5: v1(56.6,33.125) R890.1@56.6,34.5
  BOTTOM w0.5: R892.1@56.6,34.5 v1(56.6,33.125) 60.875,33.125 61.75,32.25 69.5,32.25 69.85,31.9 C783.1@69.85,31.25 ; C891.1@69.85,22.5 70.73,22.5 70.98,22.75 70.98,27.045 70.525,27.5 C782.1@70.525,28.75 70.525,29.825 69.85,30.5 C783.1@69.85,31.25 ; R899.2@72.75,31.1 71.5,31.1 71.35,31.25 C783.1@69.85,31.25
I_SEN_P_1_1: C719.2 CN508.2 R738.1 R739.1 | length 21.8
  BOTTOM w0.5: R738.1@228.25,29.4 228.25,27.27 CN508.2@230.02,25.5 230.02,22.75 230.27,22.5 C719.2@231.15,22.5 231.15,21.75 231.4,21.5 235.5,21.5 235.75,21.75 R739.1@235.75,29.4
I_SEN_P_1_2: C886.2 CN618.2 R758.1 R759.1 | length 21.8
  BOTTOM w0.5: R758.1@196,29.4 196,27.27 CN618.2@197.77,25.5 197.77,22.75 198.02,22.5 C886.2@198.9,22.5 198.9,21.75 199.15,21.5 203.25,21.5 203.5,21.75 R759.1@203.5,29.4
I_SEN_P_1_3: C888.2 CN307.2 R778.1 R779.1 | length 21.8
  BOTTOM w0.5: R778.1@108.25,29.4 108.25,27.27 CN307.2@110.02,25.5 110.02,22.75 110.27,22.5 C888.2@111.15,22.5 111.15,21.75 111.4,21.5 115.5,21.5 115.75,21.75 R779.1@115.75,29.4
I_SEN_P_1_4: C923.2 CN920.2 R951.1 R953.2 R959.1 | length 16.1
  TOP w0.25: v1(173.9,30.625) R953.2@173.9,32
  BOTTOM w0.5: R951.1@173.9,32 v1(173.9,30.625) 177.025,30.625 177.4,30.25 R959.1@177.4,28.75 176.52,28.75 176.27,28.5 176.27,22.75 176.52,22.5 C923.2@177.4,22.5
I_SEN_P_2_1: C729.2 CN509.2 R838.1 R839.1 | length 21.8
  BOTTOM w0.5: R838.1@217.5,29.4 217.5,27.27 CN509.2@219.27,25.5 219.27,22.75 219.52,22.5 C729.2@220.4,22.5 220.4,21.75 220.65,21.5 224.75,21.5 225,21.75 R839.1@225,29.4
I_SEN_P_2_2: C887.2 CN208.2 R858.1 R859.1 | length 21.8
  BOTTOM w0.5: R858.1@185.25,29.4 185.25,27.27 CN208.2@187.02,25.5 187.02,22.75 187.27,22.5 C887.2@188.15,22.5 188.15,21.75 188.4,21.5 192.375,21.5 192.75,21.875 R859.1@192.75,29.4
I_SEN_P_2_3: C889.2 CN308.2 R878.1 R879.1 | length 21.8
  BOTTOM w0.5: R878.1@97.5,29.4 97.5,27.27 CN308.2@99.27,25.5 99.27,22.75 99.52,22.5 C889.2@100.4,22.5 100.4,21.75 100.65,21.5 104.75,21.5 105,21.75 R879.1@105,29.4
I_SEN_P_2_4: C891.2 CN408.2 R898.1 R899.1 | length 21.8
  BOTTOM w0.5: R898.1@65.25,29.4 65.25,27.27 CN408.2@67.02,25.5 67.02,22.75 67.27,22.5 C891.2@68.15,22.5 68.15,21.75 68.4,21.5 72.375,21.5 72.75,21.875 R899.1@72.75,29.4
L_IN1_0-1: CN3.4 IC600.13 | length 172.6
  TOP w0.25: IC600.13@144.75,86.8 144.75,88.125 145.5,88.875 v1(145.5,95.75)
  BOTTOM w0.25: v1(145.5,95.75) 146.125,95.125 155.75,95.125 157.5,93.375 180.875,93.375 182.25,94.75 211.25,94.75 219.125,86.875 219.125,71.375 219.375,71.125 234.5,71.125 244.25,61.375 244.25,29 CN3.4@249.75,23.5
L_IN1_0-2: CN103.4 IC600.83 | length 75.4
  TOP w0.25: IC600.83@127.2,65.75 126,65.75 124.625,64.375 124.625,61.125 126.125,59.625 126.125,57.875 128.5,55.5 v1(128.5,46.375)
  BOTTOM w0.25: v1(128.5,46.375) 133.25,46.375 134.625,47.75 151.75,47.75 157,42.5 157,29.25 CN103.4@162.75,23.5
L_IN1_0-3: CN203.4 IC600.96 | length 42.6
  TOP w0.25: v1(129.75,34.625) 128.5,35.875 128.5,44.125 129.75,45.375 129.75,54.625 v1(131.25,56.125) ; IC600.96@132.75,61.2 v1(132.75,62.5)
  BOTTOM w0.25: CN203.4@129.75,23.5 v1(129.75,34.625) ; v1(131.25,56.125) 131.25,59.5 132.75,61 v1(132.75,62.5)
L_IN1_0-4: CN303.4 IC600.133 | length 151.2
  TOP w0.25: CN303.4@42.75,23.5 42.75,28.25 43.25,28.75 126.75,28.75 127.875,29.875 v1(127.875,45.75) ; IC600.133@152.8,63.25 153.625,63.25 154.75,62.125 v1(154.75,48.25)
  BOTTOM w0.25: v1(127.875,45.75) 127.875,46.75 128.125,47 133.125,47 134.375,48.25 v1(154.75,48.25)
MES_EN_0-1: CN2.8 IC600.10 | length 132.9
  TOP w0.25: v1(144.125,105.25) 144.125,98.5 147.5,95.125 147.5,89.375 146.25,88.125 IC600.10@146.25,86.8
  BOTTOM w0.25: v1(144.125,105.25) 145.625,105.25 146.375,104.5 159.875,104.5 161.625,102.75 215,102.75 220.75,108.5 220.75,124.75 228,132 CN2.8@228,138
MES_EN_0-2: CN102.8 IC600.70 | length 141.9
  TOP w0.25: v1(113.125,101.5) 113.125,81.625 114.625,80.125 114.625,74.5 v1(117.25,71.875) ; v1(122.125,71.875) 126,71.875 126.375,72.25 IC600.70@127.2,72.25
  BOTTOM w0.25: v1(113.125,101.5) 118.375,106.75 118.375,107.375 118.625,107.625 133.25,107.625 133.75,108.125 146.5,108.125 147.625,107 161.125,107 162.875,105.25 174.75,105.25 177.5,108 177.5,136.5 CN102.8@176,138 ; v1(117.25,71.875) v1(122.125,71.875)
MES_EN_0-3: CN202.8 IC600.94 | length 97.5
  TOP w0.25: CN202.8@108,138 111.125,134.875 v1(111.125,134.25) ; v1(111.25,105) 111.25,81.25 113.125,79.375 v1(113.125,69.75) ; v1(126.75,62.375) 127.625,62.375 128,62.75 131.375,62.75 131.75,62.375 IC600.94@131.75,61.2
  BOTTOM w0.25: v1(111.125,134.25) 116,129.375 116,109.75 v1(111.25,105) ; v1(113.125,69.75) 120.5,62.375 v1(126.75,62.375)
MES_EN_0-4: CN302.8 IC600.112 | length 161
  TOP w0.25: v1(70.75,70.375) v1(108.75,70.375) ; IC600.112@140.75,61.2 140.75,60.125 141.25,59.625 v1(141.25,53.875)
  BOTTOM w0.25: CN302.8@56,138 70.75,123.25 v1(70.75,70.375) ; v1(108.75,70.375) 110,70.375 118.5,61.875 118.5,57.75 120.75,55.5 126.875,55.5 128.5,53.875 v1(141.25,53.875)
N00100005: C522.1 IC600.45 R522.2 | length 6.9
  TOP w0.25: R522.2@123.85,87.75 v1(124.875,87.75) 124.875,85.5 125.625,84.75 IC600.45@127.2,84.75
  BOTTOM w0.25: C522.1@123.85,87.75 v1(124.875,87.75)
N00100006: IC600.6 R606.2 | length 7
  TOP w0.25: v1(148.25,85.5) IC600.6@148.25,86.8
  BOTTOM w0.25: v1(148.25,85.5) 148.25,86.125 150.75,88.625 R606.2@150.75,90.15
N00100007: IC600.7 R607.2 | length 3.8
  TOP w0.25: IC600.7@147.75,86.8 147.75,87.625 148.75,88.625 R607.2@148.75,90.15
N00100008: C524.2 CN105.1 R572.2 R573.1 | length 108.2
  TOP w0.25: v1(134.375,107) 132.875,105.5 132.875,95.75 136,92.625 136,92 136.15,91.85 R573.1@136.75,91.85
  BOTTOM w0.25: v1(134.375,107) 146.125,107 147.125,106 160.625,106 162.375,104.25 195.125,104.25 200,109.125 CN105.1@200,126
  BOTTOM w0.5: CN105.1@200,126 201.475,126 201.625,126.15 C524.2@202.5,126.15 R572.2@202.5,123.85
N00100009: IC600.9 R608.2 | length 4.8
  TOP w0.25: IC600.9@146.75,86.8 146.75,87.625 v1(147.375,88.25)
  BOTTOM w0.25: v1(147.375,88.25) 148.375,88.25 148.75,88.625 R608.2@148.75,90.15
N00100012: IC600.12 R609.2 | length 4
  TOP w0.25: IC600.12@145.25,86.8 145.25,87.875 146.75,89.375 R609.2@146.75,90.15
N00100014: IC600.64 Q510.2 | length 116
  TOP w0.25: v1(125.5,52.125) 125.5,55.5 124.125,56.875 124.125,58.625 122.625,60.125 122.625,62 120,64.625 120,73.125 122.125,75.25 IC600.64@127.2,75.25
  BOTTOM w0.25: v1(125.5,52.125) 125.5,51.125 125.875,50.75 127.125,50.75 127.5,50.375 132,50.375 133.25,51.625 156.125,51.625 160.125,55.625 174.125,55.625 177.125,58.625 187.375,58.625 193,64.25 193,68 193.5,68.5 197.25,68.5 197.5,68.75 Q510.2@197.5,70.225
N00100016: C530.2 IC600.41 R530.1 | length 4.4
  TOP w0.25: IC600.41@130.75,86.8 v1(130.75,89.125) R530.1@130.75,90.15
  BOTTOM w0.25: v1(130.75,89.125) C530.2@130.75,90.15
N00100017: IC600.17 R646.2 | length 3.7
  TOP w0.25: IC600.17@142.75,86.8 142.75,87.75 v1(143.125,88.125)
  BOTTOM w0.25: R646.2@142.75,90.15 142.75,88.5 v1(143.125,88.125)
N00100018: IC600.18 R604.2 | length 3.6
  TOP w0.25: IC600.18@142.25,86.8 142.25,88.2 142.75,88.7 R604.2@142.75,90.15
N00100019: IC600.19 R605.2 | length 10.5
  TOP w0.25: IC600.19@141.75,86.8 141.75,88.45 142,88.7 142,96.35 142.25,96.6 R605.2@142.75,96.6
N00100020: C546.2 CN540.1 R594.1 | length 5.6
  TOP w0.25: v1(167.23,76.35) CN540.1@167.23,78.85
  BOTTOM w0.25: R594.1@166.25,78.45 C546.2@166.25,76.35 v1(167.23,76.35)
N00100021: IC600.66 Q511.5 | length 114.1
  TOP w0.25: v1(126.75,50.125) 126.75,55.75 125.125,57.375 125.125,59.125 123.625,60.625 123.625,62.5 121,65.125 121,72.625 122.625,74.25 IC600.66@127.2,74.25
  BOTTOM w0.25: v1(126.75,50.125) 127,49.875 132.25,49.875 133.5,51.125 156.375,51.125 160.375,55.125 174.375,55.125 177.375,58.125 187.625,58.125 193.5,64 193.5,67.75 193.75,68 197.25,68 197.5,67.75 Q511.5@197.5,66.025
N00100022: R574.2 R576.1 R577.1 | length 5.9
  BOTTOM w0.25: R574.2@185.75,80.55 185.75,81.375 186,81.625 187.75,81.625 ; R576.1@188,80.35 188,81.375 ; R577.1@188,82.65 188,81.875 ; 187.75,81.625 188,81.375 ; 187.75,81.625 188,81.875 ; 188,81.375 188,81.875
N00100025: C548.2 R595.1 R596.2 | length 4.3
  BOTTOM w0.25: R596.2@168.5,78.65 R595.1@170.5,78.65 C548.2@170.5,76.35
N00100031: C545.2 IC600.29 R593.2 | length 15
  TOP w0.25: v1(135.75,84.85) 136.75,85.85 IC600.29@136.75,86.8 136.75,88.125 137.5,88.875 137.5,93 137.25,93.25 v1(136.75,93.25)
  BOTTOM w0.25: R593.2@134,94.9 134,93.5 134.25,93.25 v1(136.75,93.25) ; C545.2@134.75,84.85 v1(135.75,84.85)
N00100035: R594.2 R596.1 R597.1 | length 5.9
  BOTTOM w0.25: R594.2@166.25,80.55 166.25,81.375 166.5,81.625 168.25,81.625 ; R596.1@168.5,80.35 168.5,81.375 ; R597.1@168.5,82.65 168.5,81.875 ; 168.25,81.625 168.5,81.375 ; 168.25,81.625 168.5,81.875 ; 168.5,81.375 168.5,81.875
N00100036: C523.1 IC600.57 R523.2 | length 4.5
  TOP w0.25: R523.2@123.85,79 v1(124.875,79) 125.125,78.75 IC600.57@127.2,78.75
  BOTTOM w0.25: C523.1@123.85,79 v1(124.875,79)
N00100037: C605.2 R663.1 | length 2.2
  BOTTOM w0.25: C605.2@127.975,85.25 R663.1@130.15,85.25
N00100038: IC600.65 Q510.5 | length 118.3
  TOP w0.25: v1(126.125,51.5) 126.125,55.625 124.625,57.125 124.625,58.875 123.125,60.375 123.125,62.25 120.5,64.875 120.5,72.875 122.375,74.75 IC600.65@127.2,74.75
  BOTTOM w0.25: v1(126.125,51.5) 127.125,51.5 127.75,50.875 131.75,50.875 133,52.125 155.875,52.125 159.875,56.125 173.875,56.125 176.875,59.125 187.125,59.125 192.5,64.5 192.5,68.25 193.5,69.25 193.5,73.5 193.75,73.75 197.25,73.75 197.5,73.5 Q510.5@197.5,72.275
N00100039: IC600.162 R600.2 | length 3.2
  TOP w0.25: IC600.162@152.8,77.75 v1(154.125,77.75)
  BOTTOM w0.25: v1(154.125,77.75) 154.875,77.75 155.15,78.025 R600.2@155.15,78.75
N00100040: IC600.63 Q511.2 | length 113.2
  TOP w0.25: v1(124.875,51) 124.875,55.375 123.625,56.625 123.625,58.375 122.125,59.875 122.125,61.75 119.5,64.375 119.5,73.375 121.875,75.75 IC600.63@127.2,75.75
  BOTTOM w0.25: v1(124.875,51) 126.625,49.25 132.375,49.25 133.75,50.625 156.625,50.625 160.625,54.625 174.625,54.625 177.625,57.625 187.875,57.625 192.5,62.25 196.625,62.25 197.5,63.125 Q511.2@197.5,63.975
